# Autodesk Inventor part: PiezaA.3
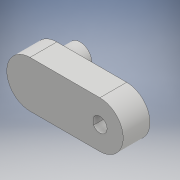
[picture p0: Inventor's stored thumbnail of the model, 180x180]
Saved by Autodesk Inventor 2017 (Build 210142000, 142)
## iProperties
Part Number: PiezaA.3
Material: Genérico
Document SubType Name: Modeling
Designer: Jaime
Density: 1 g/cm^3
Appearance: Valor por defecto
Mass: 24.0111 g
Surface Area: 58.6407 cm^2
Volume: 24.0111 cm^3
Author: Jaime
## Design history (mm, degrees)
sketch "Boceto1"
  geometry: L1 (0, 10)-(30, 10); L2 (0, -10)-(30, -10); A1 r 10 centre (30, 0) between (30, -10) and (30, 10); A2 r 10 centre (0, 0) between (0, 10) and (0, -10); 1 further point
  constraints: 4 end point, 4 point on circle, 4 tangent, 2 centre point, 2 horizontal alignment, 1 coincident
  dimensions: "d0" = 20 diameter of A1; "d34" = 20 diameter of A2; "d35" = 30 distance of A1.centre A2.centre
extrude "Extrusión1" new body sketch "Boceto1" distance "d3" = 11.5; taper "d4" = 0 deg
sketch "Boceto2"
  geometry: C1 r 7 at (-30, 0); A1 r 10 centre (-30, 0) between (-30, 10) and (-30, -10) reference; 1 further point
  constraints: 1 centre point, 1 coincident, 1 point on circle
  dimensions: "d8" = 14 diameter of C1
extrude "Extrusión2" join sketch "Boceto2" distance "d5" = 2; taper "d6" = 0 deg
sketch "Boceto4"
  geometry: C1 r 5 at (0, 0); C2 r 7 at (0, 0) reference; 1 further point
  constraints: 1 centre point, 1 concentric
  dimensions: "d9" = 10 diameter of C1
extrude "Extrusión3" join sketch "Boceto4" distance "d10" = 8; taper "d11" = 0 deg
sketch "Boceto8"
  geometry: L1 (-2.7, -1.523)-(-2.7, 1.523); L2 (0, -10)-(-30, -10) reference; A1 r 3.1 centre (0, 0) between (-2.7, -1.523) and (-2.7, 1.523); 1 further point
  constraints: 2 end point, 2 point on circle, 1 centre point, 1 coincident, 1 perpendicular, 1 vertical
  dimensions: "d36" = 6.2 diameter of A1; "d37" = 2.7 distance from line of L1 A1.centre
extrude "Extrusión7" cut sketch "Boceto8" distance "d38" = 8.5; taper "d39" = 0 deg
node "Sólido1"
other parameters: "Taladros" = 3 [user parameter], "Agrueso" = 15 [user parameter], "Bgrueso" = 15 [user parameter]
